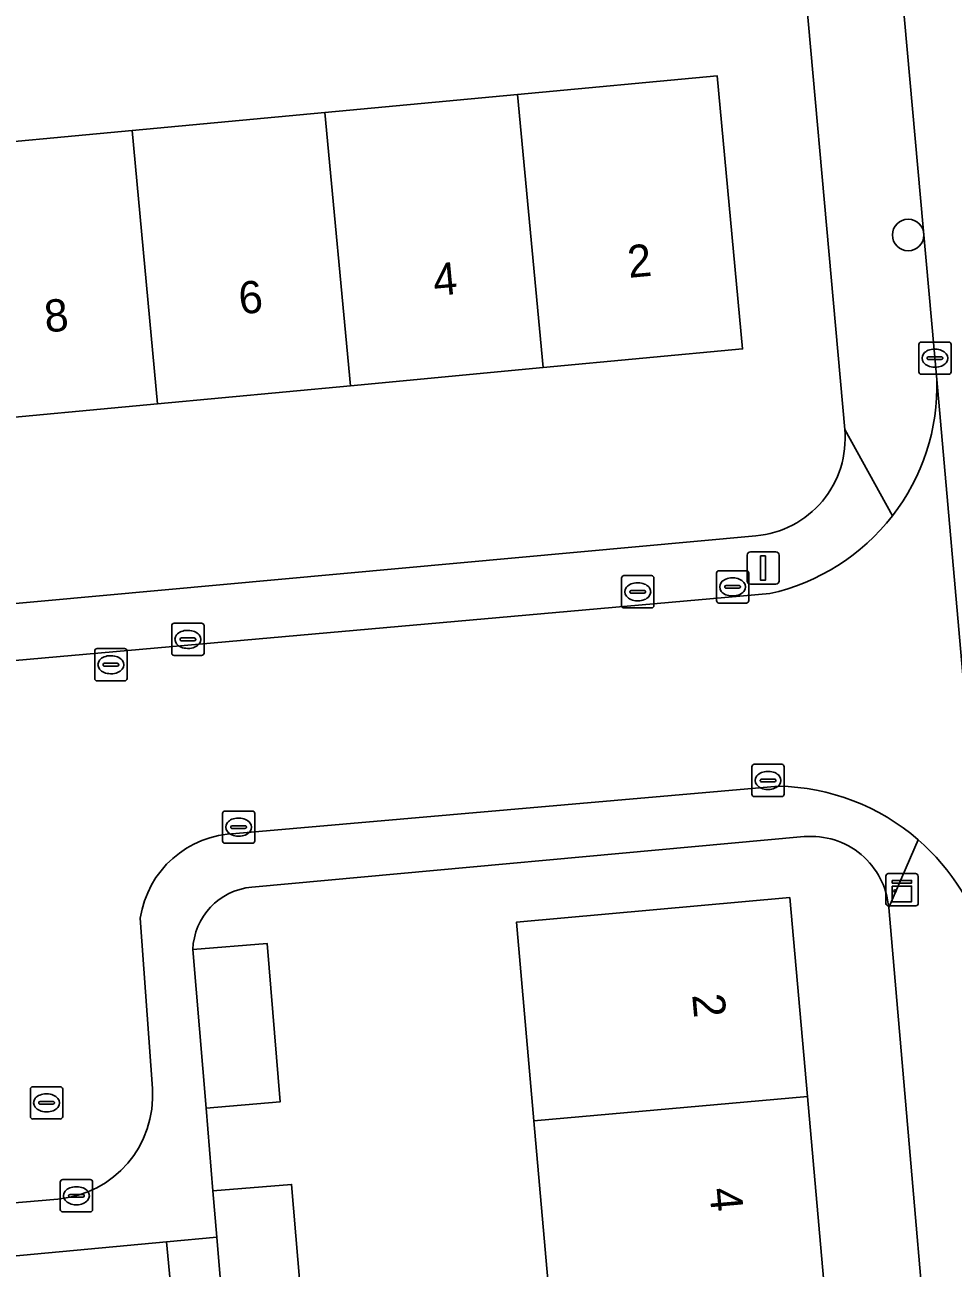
# Model space of a CAD drawing. Extents: x 160554 to 161248, y 385329 to 386506.
# Drawn here: x 160890.27 to 160919.04, y 385530.83 to 385569.34 of the extents above; entities that cross this region are included whole.
import ezdxf

# ---------------------------------------------------------------- set-up
doc = ezdxf.new("R2010")
doc.units = 0
for name, color, linetype in [('IMGEO_Boom', 7, 'Continuous'), ('IMGEO_Brandkraan', 7, 'Continuous'), ('IMGEO_Erf', 7, 'Continuous'), ('IMGEO_Kast', 7, 'Continuous'), ('IMGEO_Kolk', 7, 'Continuous'), ('IMGEO_Lichtmast', 7, 'Continuous'), ('IMGEO_Pand', 7, 'Continuous'), ('IMGEO_Pand_nummerreeks', 7, 'Continuous'), ('IMGEO_Rijbaan_lokaal_open', 7, 'Continuous'), ('IMGEO_Rioolput', 7, 'Continuous'), ('IMGEO_Voetpad_open', 7, 'Continuous')]:
    doc.layers.add(name, color=color, linetype=linetype)

msp = doc.modelspace()

# ---------------------------------------------------------------- linework, layer by layer
at = {"layer": 'IMGEO_Boom'}
msp.add_circle((160917.643, 385562.833), 0.489, dxfattribs=at)
at = {"layer": 'IMGEO_Brandkraan'}
for p, q in [((160908.835, 385552.279), (160909.687, 385552.279)), ((160908.76, 385551.353), (160908.76, 385552.205)), ((160909.248, 385552.059), (160909.273, 385552.059)), ((160909.761, 385552.205), (160909.761, 385551.353)), ((160909.019, 385551.773), (160909.019, 385551.785)), ((160909.457, 385551.736), (160909.059, 385551.736)), ((160909.062, 385551.822), (160909.46, 385551.822)), ((160909.271, 385551.499), (160909.246, 385551.499)), ((160909.503, 385551.785), (160909.503, 385551.773)), ((160909.687, 385551.279), (160908.835, 385551.279)), ((160892.431, 385549.094), (160892.431, 385549.946)), ((160892.506, 385550.02), (160893.358, 385550.02)), ((160893.432, 385549.946), (160893.432, 385549.094)), ((160892.733, 385549.563), (160893.131, 385549.563)), ((160892.919, 385549.8), (160892.944, 385549.8)), ((160892.69, 385549.514), (160892.69, 385549.526)), ((160893.128, 385549.477), (160892.73, 385549.477)), ((160892.942, 385549.24), (160892.917, 385549.24)), ((160893.174, 385549.526), (160893.174, 385549.514)), ((160893.358, 385549.02), (160892.506, 385549.02))]:
    msp.add_line(p, q, dxfattribs=at)
for points in [[(160908.835, 385552.279), (160909.687, 385552.279)], [(160908.76, 385551.353), (160908.76, 385552.205)], [(160909.761, 385552.205), (160909.761, 385551.353)], [(160909.687, 385551.279), (160908.835, 385551.279)], [(160892.431, 385549.094), (160892.431, 385549.946)], [(160892.506, 385550.02), (160893.358, 385550.02)], [(160893.432, 385549.946), (160893.432, 385549.094)], [(160893.358, 385549.02), (160892.506, 385549.02)]]:
    msp.add_lwpolyline(points, dxfattribs=at)
for centre, radius, start, end in [((160908.837, 385552.203), 0.0765, 91.552, 178.448), ((160908.837, 385552.203), 0.0765, 91.552, 178.448), ((160909.685, 385552.203), 0.0765, 1.552, 88.448), ((160909.685, 385552.203), 0.0765, 1.552, 88.448), ((160909.059, 385551.782), 0.0403, 85.8775, 175.7526), ((160909.056, 385551.772), 0.0366, 178.938, 274.7102), ((160909.46, 385551.779), 0.043, 264.8664, 352.4533), ((160909.464, 385551.784), 0.0386, 1.7309, 96.639), ((160908.837, 385551.355), 0.0765, 181.552, 268.448), ((160908.837, 385551.355), 0.0765, 181.552, 268.448), ((160909.685, 385551.355), 0.0765, 271.552, 358.448), ((160909.685, 385551.355), 0.0765, 271.552, 358.448), ((160892.508, 385549.944), 0.0765, 91.552, 178.448), ((160892.508, 385549.944), 0.0765, 91.552, 178.448), ((160893.356, 385549.944), 0.0765, 1.552, 88.448), ((160893.356, 385549.944), 0.0765, 1.552, 88.448), ((160892.73, 385549.523), 0.0403, 85.8775, 175.7526), ((160893.135, 385549.525), 0.0386, 1.7309, 96.639), ((160892.727, 385549.513), 0.0366, 178.938, 274.7102), ((160893.131, 385549.52), 0.043, 264.8664, 352.4533), ((160892.508, 385549.096), 0.0765, 181.552, 268.448), ((160892.508, 385549.096), 0.0765, 181.552, 268.448), ((160893.356, 385549.096), 0.0765, 271.552, 358.448), ((160893.356, 385549.096), 0.0765, 271.552, 358.448)]:
    msp.add_arc(centre, radius, start, end, dxfattribs=at)
for centre, major_axis, ratio, start_param, end_param in [((160909.247, 385551.779), (-0.387, 0.002), 0.722429, 4.712389, 7.853982), ((160909.272, 385551.779), (-0.39, 0.002), 0.717154, 1.570796, 4.712389), ((160892.918, 385549.52), (-0.387, 0.002), 0.722429, 4.712389, 7.853982), ((160892.943, 385549.52), (-0.39, 0.002), 0.717154, 1.570796, 4.712389)]:
    msp.add_ellipse(centre, major_axis=major_axis, ratio=ratio, start_param=start_param, end_param=end_param, dxfattribs=at)
at = {"layer": 'IMGEO_Erf'}
for points in [[(160915.678, 385556.807), (160914.058, 385574.884)], [(160861.315, 385572.826), (160862.693, 385557.771), (160864.008, 385557.909), (160863.508, 385563.248), (160869.693, 385563.827), (160875.667, 385564.387), (160875.425, 385566.97), (160881.399, 385567.53), (160881.641, 385564.947), (160887.615, 385565.506), (160893.588, 385566.066), (160899.562, 385566.625), (160905.536, 385567.185), (160911.72, 385567.764)], [(160911.72, 385567.764), (160912.513, 385559.301), (160906.329, 385558.722), (160900.355, 385558.162), (160894.381, 385557.603), (160888.408, 385557.043), (160882.434, 385556.484), (160876.46, 385555.924), (160870.486, 385555.364), (160864.477, 385554.802), (160864.993, 385549.134), (160912.922, 385553.512)], [(160914.423, 385544.194), (160897.297, 385542.63)], [(160922.169, 385482.49), (160920.66, 385500), (160917.04, 385541.995)], [(160895.471, 385540.695), (160897.773, 385540.887), (160898.182, 385535.98), (160895.88, 385535.788), (160896.095, 385533.221), (160898.533, 385533.424), (160898.921, 385528.774)], [(160895.014, 385527.83), (160894.659, 385531.64), (160866.822, 385529.049)]]:
    msp.add_lwpolyline(points, dxfattribs=at)
msp.add_lwpolyline([(160907.099, 385523.44), (160906.571, 385529.417), (160906.043, 385535.394), (160905.5, 385541.541), (160913.975, 385542.309), (160914.52, 385536.143), (160915.048, 385530.166), (160915.575, 385524.189), (160916.103, 385518.213), (160916.631, 385512.236), (160917.159, 385506.259), (160917.687, 385500.282), (160917.712, 385500), (160918.215, 385494.306), (160918.76, 385488.141), (160910.284, 385487.387), (160909.739, 385493.557), (160909.211, 385499.533), (160909.17, 385500), (160908.683, 385505.51), (160908.155, 385511.487), (160907.627, 385517.464)], close=True, dxfattribs=at)
for centre, radius, start, end in [((160912.657, 385556.534), 3.033, 275.0141, 5.1664), ((160914.634, 385541.789), 2.414, 4.8991, 95.0219), ((160897.488, 385540.621), 2.018, 95.4245, 177.8956)]:
    msp.add_arc(centre, radius, start, end, dxfattribs=at)
at = {"layer": 'IMGEO_Kast'}
for p, q in [((160917.028, 385543.05), (160917.869, 385543.05)), ((160917.869, 385543.05), (160917.028, 385543.05)), ((160916.953, 385542.125), (160916.953, 385542.966)), ((160916.953, 385542.966), (160916.953, 385542.125)), ((160917.953, 385542.975), (160917.953, 385542.134)), ((160917.953, 385542.134), (160917.953, 385542.975)), ((160917.878, 385542.05), (160917.037, 385542.05)), ((160917.037, 385542.05), (160917.878, 385542.05))]:
    msp.add_line(p, q, dxfattribs=at)
for points in [[(160917.148, 385542.84), (160917.748, 385542.84), (160917.748, 385542.755), (160917.148, 385542.755), (160917.148, 385542.84)], [(160917.148, 385542.665), (160917.748, 385542.665), (160917.748, 385542.176), (160917.148, 385542.176), (160917.148, 385542.665)]]:
    msp.add_lwpolyline(points, dxfattribs=at)
msp.add_circle((160917.232, 385542.514), 0.0377, dxfattribs=at)
for centre, start, end in [((160917.031, 385542.972), 92.4484, 184.2845), ((160917.031, 385542.972), 92.4484, 184.2845), ((160917.875, 385542.972), 2.4484, 94.2845), ((160917.875, 385542.972), 2.4484, 94.2845), ((160917.031, 385542.128), 182.4484, 274.2845), ((160917.031, 385542.128), 182.4484, 274.2845), ((160917.875, 385542.128), 272.4484, 4.2845), ((160917.875, 385542.128), 272.4484, 4.2845)]:
    msp.add_arc(centre, 0.0779, start, end, dxfattribs=at)
at = {"layer": 'IMGEO_Kolk'}
for p, q in [((160917.972, 385558.59), (160917.972, 385559.442)), ((160918.047, 385559.516), (160918.899, 385559.516)), ((160918.46, 385559.296), (160918.485, 385559.296)), ((160918.973, 385559.442), (160918.973, 385558.59)), ((160918.231, 385559.01), (160918.231, 385559.022)), ((160918.669, 385558.973), (160918.271, 385558.973)), ((160918.274, 385559.059), (160918.672, 385559.059)), ((160918.715, 385559.022), (160918.715, 385559.01)), ((160918.899, 385558.516), (160918.047, 385558.516)), ((160918.483, 385558.736), (160918.458, 385558.736)), ((160911.701, 385551.505), (160911.701, 385552.357)), ((160911.776, 385552.431), (160912.628, 385552.431)), ((160912.702, 385552.357), (160912.702, 385551.505)), ((160911.96, 385551.925), (160911.96, 385551.937)), ((160912.398, 385551.888), (160912, 385551.888)), ((160912.003, 385551.974), (160912.401, 385551.974)), ((160912.189, 385552.211), (160912.214, 385552.211)), ((160912.444, 385551.937), (160912.444, 385551.925)), ((160912.212, 385551.651), (160912.187, 385551.651)), ((160912.628, 385551.431), (160911.776, 385551.431)), ((160894.818, 385549.879), (160894.818, 385550.731)), ((160894.893, 385550.805), (160895.745, 385550.805)), ((160895.819, 385550.731), (160895.819, 385549.879)), ((160895.12, 385550.348), (160895.518, 385550.348)), ((160895.306, 385550.585), (160895.331, 385550.585)), ((160895.077, 385550.299), (160895.077, 385550.311)), ((160895.515, 385550.262), (160895.117, 385550.262)), ((160895.329, 385550.025), (160895.304, 385550.025)), ((160895.561, 385550.311), (160895.561, 385550.299)), ((160895.745, 385549.805), (160894.893, 385549.805)), ((160912.799, 385545.509), (160912.799, 385546.361)), ((160912.874, 385546.435), (160913.726, 385546.435)), ((160913.287, 385546.215), (160913.312, 385546.215)), ((160913.8, 385546.361), (160913.8, 385545.509)), ((160913.058, 385545.929), (160913.058, 385545.941)), ((160913.496, 385545.892), (160913.098, 385545.892)), ((160913.101, 385545.978), (160913.499, 385545.978)), ((160913.542, 385545.941), (160913.542, 385545.929)), ((160913.726, 385545.435), (160912.874, 385545.435)), ((160913.31, 385545.655), (160913.285, 385545.655)), ((160896.466, 385544.988), (160897.318, 385544.988)), ((160896.391, 385544.062), (160896.391, 385544.914)), ((160896.879, 385544.768), (160896.904, 385544.768)), ((160897.392, 385544.914), (160897.392, 385544.062)), ((160896.65, 385544.482), (160896.65, 385544.494)), ((160897.088, 385544.445), (160896.69, 385544.445)), ((160896.693, 385544.531), (160897.091, 385544.531)), ((160896.902, 385544.208), (160896.877, 385544.208)), ((160897.134, 385544.494), (160897.134, 385544.482)), ((160897.318, 385543.988), (160896.466, 385543.988)), ((160891.363, 385532.644), (160891.363, 385533.496)), ((160891.438, 385533.57), (160892.29, 385533.57)), ((160892.364, 385533.496), (160892.364, 385532.644)), ((160891.622, 385533.064), (160891.622, 385533.076)), ((160892.06, 385533.027), (160891.662, 385533.027)), ((160891.665, 385533.113), (160892.063, 385533.113)), ((160891.851, 385533.35), (160891.876, 385533.35)), ((160892.106, 385533.076), (160892.106, 385533.064)), ((160891.874, 385532.79), (160891.849, 385532.79)), ((160892.29, 385532.57), (160891.438, 385532.57))]:
    msp.add_line(p, q, dxfattribs=at)
for points in [[(160917.972, 385558.59), (160917.972, 385559.442)], [(160918.047, 385559.516), (160918.899, 385559.516)], [(160918.973, 385559.442), (160918.973, 385558.59)], [(160918.899, 385558.516), (160918.047, 385558.516)], [(160911.701, 385551.505), (160911.701, 385552.357)], [(160911.776, 385552.431), (160912.628, 385552.431)], [(160912.702, 385552.357), (160912.702, 385551.505)], [(160912.628, 385551.431), (160911.776, 385551.431)], [(160894.818, 385549.879), (160894.818, 385550.731)], [(160894.893, 385550.805), (160895.745, 385550.805)], [(160895.819, 385550.731), (160895.819, 385549.879)], [(160895.745, 385549.805), (160894.893, 385549.805)], [(160912.799, 385545.509), (160912.799, 385546.361)], [(160912.874, 385546.435), (160913.726, 385546.435)], [(160913.8, 385546.361), (160913.8, 385545.509)], [(160913.726, 385545.435), (160912.874, 385545.435)], [(160896.466, 385544.988), (160897.318, 385544.988)], [(160896.391, 385544.062), (160896.391, 385544.914)], [(160897.392, 385544.914), (160897.392, 385544.062)], [(160897.318, 385543.988), (160896.466, 385543.988)], [(160891.363, 385532.644), (160891.363, 385533.496)], [(160891.438, 385533.57), (160892.29, 385533.57)], [(160892.364, 385533.496), (160892.364, 385532.644)], [(160892.29, 385532.57), (160891.438, 385532.57)]]:
    msp.add_lwpolyline(points, dxfattribs=at)
for centre, radius, start, end in [((160918.049, 385559.44), 0.0765, 91.552, 178.448), ((160918.049, 385559.44), 0.0765, 91.552, 178.448), ((160918.897, 385559.44), 0.0765, 1.552, 88.448), ((160918.897, 385559.44), 0.0765, 1.552, 88.448), ((160918.271, 385559.019), 0.0403, 85.8775, 175.7526), ((160918.268, 385559.009), 0.0366, 178.938, 274.7102), ((160918.672, 385559.016), 0.043, 264.8664, 352.4533), ((160918.676, 385559.021), 0.0386, 1.7309, 96.639), ((160918.049, 385558.592), 0.0765, 181.552, 268.448), ((160918.049, 385558.592), 0.0765, 181.552, 268.448), ((160918.897, 385558.592), 0.0765, 271.552, 358.448), ((160918.897, 385558.592), 0.0765, 271.552, 358.448), ((160911.778, 385552.355), 0.0765, 91.552, 178.448), ((160911.778, 385552.355), 0.0765, 91.552, 178.448), ((160912.626, 385552.355), 0.0765, 1.552, 88.448), ((160912.626, 385552.355), 0.0765, 1.552, 88.448), ((160912, 385551.934), 0.0403, 85.8775, 175.7526), ((160911.997, 385551.924), 0.0366, 178.938, 274.7102), ((160912.401, 385551.931), 0.043, 264.8664, 352.4533), ((160912.405, 385551.936), 0.0386, 1.7309, 96.639), ((160911.778, 385551.507), 0.0765, 181.552, 268.448), ((160911.778, 385551.507), 0.0765, 181.552, 268.448), ((160912.626, 385551.507), 0.0765, 271.552, 358.448), ((160912.626, 385551.507), 0.0765, 271.552, 358.448), ((160894.895, 385550.729), 0.0765, 91.552, 178.448), ((160894.895, 385550.729), 0.0765, 91.552, 178.448), ((160895.743, 385550.729), 0.0765, 1.552, 88.448), ((160895.743, 385550.729), 0.0765, 1.552, 88.448), ((160895.117, 385550.308), 0.0403, 85.8775, 175.7526), ((160895.522, 385550.31), 0.0386, 1.7309, 96.639), ((160895.114, 385550.298), 0.0366, 178.938, 274.7102), ((160895.518, 385550.305), 0.043, 264.8664, 352.4533), ((160894.895, 385549.881), 0.0765, 181.552, 268.448), ((160894.895, 385549.881), 0.0765, 181.552, 268.448), ((160895.743, 385549.881), 0.0765, 271.552, 358.448), ((160895.743, 385549.881), 0.0765, 271.552, 358.448), ((160912.876, 385546.359), 0.0765, 91.552, 178.448), ((160912.876, 385546.359), 0.0765, 91.552, 178.448), ((160913.724, 385546.359), 0.0765, 1.552, 88.448), ((160913.724, 385546.359), 0.0765, 1.552, 88.448), ((160913.098, 385545.938), 0.0403, 85.8775, 175.7526), ((160913.095, 385545.928), 0.0366, 178.938, 274.7102), ((160913.499, 385545.935), 0.043, 264.8664, 352.4533), ((160913.503, 385545.94), 0.0386, 1.7309, 96.639), ((160912.876, 385545.511), 0.0765, 181.552, 268.448), ((160912.876, 385545.511), 0.0765, 181.552, 268.448), ((160913.724, 385545.511), 0.0765, 271.552, 358.448), ((160913.724, 385545.511), 0.0765, 271.552, 358.448), ((160896.468, 385544.912), 0.0765, 91.552, 178.448), ((160896.468, 385544.912), 0.0765, 91.552, 178.448), ((160897.316, 385544.912), 0.0765, 1.552, 88.448), ((160897.316, 385544.912), 0.0765, 1.552, 88.448), ((160896.69, 385544.491), 0.0403, 85.8775, 175.7526), ((160896.687, 385544.481), 0.0366, 178.938, 274.7102), ((160897.091, 385544.488), 0.043, 264.8664, 352.4533), ((160897.095, 385544.493), 0.0386, 1.7309, 96.639), ((160896.468, 385544.064), 0.0765, 181.552, 268.448), ((160896.468, 385544.064), 0.0765, 181.552, 268.448), ((160897.316, 385544.064), 0.0765, 271.552, 358.448), ((160897.316, 385544.064), 0.0765, 271.552, 358.448), ((160891.44, 385533.494), 0.0765, 91.552, 178.448), ((160891.44, 385533.494), 0.0765, 91.552, 178.448), ((160892.288, 385533.494), 0.0765, 1.552, 88.448), ((160892.288, 385533.494), 0.0765, 1.552, 88.448), ((160891.662, 385533.073), 0.0403, 85.8775, 175.7526), ((160891.659, 385533.063), 0.0366, 178.938, 274.7102), ((160892.063, 385533.07), 0.043, 264.8664, 352.4533), ((160892.067, 385533.075), 0.0386, 1.7309, 96.639), ((160891.44, 385532.646), 0.0765, 181.552, 268.448), ((160891.44, 385532.646), 0.0765, 181.552, 268.448), ((160892.288, 385532.646), 0.0765, 271.552, 358.448), ((160892.288, 385532.646), 0.0765, 271.552, 358.448)]:
    msp.add_arc(centre, radius, start, end, dxfattribs=at)
for centre, major_axis, ratio, start_param, end_param in [((160918.459, 385559.016), (-0.387, 0.002), 0.722429, 4.712389, 7.853982), ((160918.484, 385559.016), (-0.39, 0.002), 0.717154, 1.570796, 4.712389), ((160912.188, 385551.931), (-0.387, 0.002), 0.722429, 4.712389, 7.853982), ((160912.213, 385551.931), (-0.39, 0.002), 0.717154, 1.570796, 4.712389), ((160895.305, 385550.305), (-0.387, 0.002), 0.722429, 4.712389, 7.853982), ((160895.33, 385550.305), (-0.39, 0.002), 0.717154, 1.570796, 4.712389), ((160913.286, 385545.935), (-0.387, 0.002), 0.722429, 4.712389, 7.853982), ((160913.311, 385545.935), (-0.39, 0.002), 0.717154, 1.570796, 4.712389), ((160896.878, 385544.488), (-0.387, 0.002), 0.722429, 4.712389, 7.853982), ((160896.903, 385544.488), (-0.39, 0.002), 0.717154, 1.570796, 4.712389), ((160891.85, 385533.07), (-0.387, 0.002), 0.722429, 4.712389, 7.853982), ((160891.875, 385533.07), (-0.39, 0.002), 0.717154, 1.570796, 4.712389)]:
    msp.add_ellipse(centre, major_axis=major_axis, ratio=ratio, start_param=start_param, end_param=end_param, dxfattribs=at)
at = {"layer": 'IMGEO_Lichtmast'}
for p, q in [((160912.651, 385552.113), (160912.651, 385552.913)), ((160912.651, 385552.913), (160912.651, 385552.113)), ((160912.751, 385553.013), (160913.541, 385553.013)), ((160913.541, 385553.013), (160912.751, 385553.013)), ((160913.641, 385552.913), (160913.641, 385552.113)), ((160913.641, 385552.113), (160913.641, 385552.913)), ((160913.541, 385552.013), (160912.751, 385552.013)), ((160912.751, 385552.013), (160913.541, 385552.013))]:
    msp.add_line(p, q, dxfattribs=at)
msp.add_lwpolyline([(160913.071, 385552.888), (160913.221, 385552.888), (160913.221, 385552.138), (160913.071, 385552.138), (160913.071, 385552.888)], dxfattribs=at)
for centre, start, end in [((160912.751, 385552.913), 90, 180), ((160912.751, 385552.913), 90, 180), ((160913.541, 385552.913), 0, 90), ((160913.541, 385552.913), 360, 90), ((160912.751, 385552.113), 180, 270), ((160912.751, 385552.113), 180, 270), ((160913.541, 385552.113), 270, 0), ((160913.541, 385552.113), 270, 0)]:
    msp.add_arc(centre, 0.1, start, end, dxfattribs=at)
at = {"layer": 'IMGEO_Pand'}
for points in [[(160906.329, 385558.722), (160912.513, 385559.301), (160911.72, 385567.764), (160905.536, 385567.185)], [(160905.536, 385567.185), (160899.562, 385566.625), (160900.355, 385558.162), (160906.329, 385558.722)], [(160899.562, 385566.625), (160893.588, 385566.066), (160894.381, 385557.603), (160900.355, 385558.162)], [(160893.588, 385566.066), (160887.615, 385565.506), (160888.408, 385557.043), (160894.381, 385557.603)], [(160914.52, 385536.143), (160913.975, 385542.309), (160905.5, 385541.541), (160906.043, 385535.394)], [(160895.88, 385535.788), (160898.182, 385535.98), (160897.773, 385540.887), (160895.471, 385540.695)], [(160906.043, 385535.394), (160906.571, 385529.417), (160915.048, 385530.166), (160914.52, 385536.143)], [(160896.215, 385531.785), (160896.484, 385528.559), (160898.921, 385528.774), (160898.533, 385533.424), (160896.095, 385533.221)]]:
    msp.add_lwpolyline(points, close=True, dxfattribs=at)
at = {"layer": 'IMGEO_Rijbaan_lokaal_open'}
for points in [[(160925.621, 385558.308), (160924.059, 385575.413), (160923.718, 385579.136), (160923.487, 385581.67), (160921.484, 385603.875), (160921.344, 385605.542), (160914.387, 385604.81), (160914.572, 385603.534), (160914.741, 385601.627), (160916.313, 385583.041), (160916.536, 385580.505), (160916.636, 385579.396), (160916.744, 385578.2), (160917.103, 385574.214), (160918.533, 385558.353), (160920.088, 385540.64), (160921.02, 385529.968), (160921.23, 385527.569), (160921.415, 385525.719), (160922.559, 385513.431)], [(160920.088, 385540.64), (160918.533, 385558.353)], [(160913.355, 385551.724), (160871.806, 385548.04)], [(160896.809, 385544.291), (160913.629, 385545.756)], [(160894.217, 385536.396), (160893.843, 385541.672)], [(160873.261, 385531.435), (160891.284, 385532.967)]]:
    msp.add_lwpolyline(points, dxfattribs=at)
for centre, radius, start, end in [((160911.935, 385558.171), 6.601, 322.238, 1.5771), ((160911.935, 385558.168), 6.598, 282.4267, 322.2596), ((160913.502, 385538.955), 6.802, 49.1441, 88.9266), ((160896.891, 385541.209), 3.083, 91.5249, 171.3646), ((160913.5, 385538.961), 6.798, 14.297, 49.1044), ((160891.013, 385536.168), 3.212, 274.8457, 4.0702)]:
    msp.add_arc(centre, radius, start, end, dxfattribs=at)
at = {"layer": 'IMGEO_Rioolput'}
for p, q in [((160890.437, 385535.522), (160890.437, 385536.374)), ((160890.512, 385536.448), (160891.364, 385536.448)), ((160890.925, 385536.228), (160890.95, 385536.228)), ((160891.438, 385536.374), (160891.438, 385535.522)), ((160890.696, 385535.942), (160890.696, 385535.954)), ((160891.134, 385535.905), (160890.736, 385535.905)), ((160890.739, 385535.991), (160891.137, 385535.991)), ((160891.18, 385535.954), (160891.18, 385535.942)), ((160891.364, 385535.448), (160890.512, 385535.448)), ((160890.948, 385535.668), (160890.923, 385535.668))]:
    msp.add_line(p, q, dxfattribs=at)
for points in [[(160890.437, 385535.522), (160890.437, 385536.374)], [(160890.512, 385536.448), (160891.364, 385536.448)], [(160891.438, 385536.374), (160891.438, 385535.522)], [(160891.364, 385535.448), (160890.512, 385535.448)]]:
    msp.add_lwpolyline(points, dxfattribs=at)
for centre, radius, start, end in [((160890.514, 385536.372), 0.0765, 91.552, 178.448), ((160890.514, 385536.372), 0.0765, 91.552, 178.448), ((160891.362, 385536.372), 0.0765, 1.552, 88.448), ((160891.362, 385536.372), 0.0765, 1.552, 88.448), ((160890.736, 385535.951), 0.0403, 85.8775, 175.7526), ((160890.733, 385535.941), 0.0366, 178.938, 274.7102), ((160891.137, 385535.948), 0.043, 264.8664, 352.4533), ((160891.141, 385535.953), 0.0386, 1.7309, 96.639), ((160890.514, 385535.524), 0.0765, 181.552, 268.448), ((160890.514, 385535.524), 0.0765, 181.552, 268.448), ((160891.362, 385535.524), 0.0765, 271.552, 358.448), ((160891.362, 385535.524), 0.0765, 271.552, 358.448)]:
    msp.add_arc(centre, radius, start, end, dxfattribs=at)
for centre, major_axis, ratio, start_param, end_param in [((160890.924, 385535.948), (-0.387, 0.002), 0.722429, 4.712389, 7.853982), ((160890.949, 385535.948), (-0.39, 0.002), 0.717154, 1.570796, 4.712389)]:
    msp.add_ellipse(centre, major_axis=major_axis, ratio=ratio, start_param=start_param, end_param=end_param, dxfattribs=at)
at = {"layer": 'IMGEO_Voetpad_open'}
for points in [[(160911.465, 385603.818), (160913.071, 385585.893), (160913.218, 385584.262), (160913.415, 385582.06), (160913.661, 385579.318), (160913.808, 385577.673), (160914.058, 385574.884), (160915.678, 385556.807), (160917.153, 385554.129)], [(160918.533, 385558.353), (160917.103, 385574.214), (160916.744, 385578.2), (160916.636, 385579.396), (160916.536, 385580.505)], [(160917.153, 385554.129), (160915.678, 385556.807)], [(160912.922, 385553.512), (160864.993, 385549.134), (160863.436, 385548.992), (160864.998, 385530.768), (160865.469, 385525.276), (160867.099, 385525.38), (160866.822, 385529.049), (160894.659, 385531.64), (160896.215, 385531.785), (160896.095, 385533.221), (160895.88, 385535.788), (160895.471, 385540.695)], [(160871.806, 385548.04), (160913.355, 385551.724)], [(160913.629, 385545.756), (160896.809, 385544.291)], [(160897.297, 385542.63), (160914.423, 385544.194)], [(160917.951, 385544.1), (160917.04, 385541.995), (160920.66, 385500), (160922.169, 385482.49), (160925.231, 385482.784), (160923.776, 385500), (160923.539, 385502.802), (160922.751, 385512.494)], [(160917.04, 385541.995), (160917.951, 385544.1)], [(160893.843, 385541.672), (160894.217, 385536.396)], [(160891.284, 385532.967), (160873.261, 385531.435)], [(160896.484, 385528.559), (160896.215, 385531.785), (160894.659, 385531.64), (160895.014, 385527.83)]]:
    msp.add_lwpolyline(points, dxfattribs=at)
for centre, radius, start, end in [((160911.935, 385558.171), 6.601, 322.238, 1.5771), ((160912.657, 385556.534), 3.033, 275.0141, 5.1664), ((160911.935, 385558.168), 6.598, 282.4267, 322.2596), ((160913.502, 385538.955), 6.802, 49.1441, 88.9266), ((160896.891, 385541.209), 3.083, 91.5249, 171.3646), ((160914.634, 385541.789), 2.414, 4.8991, 95.0219), ((160913.5, 385538.961), 6.798, 14.297, 49.1044), ((160897.488, 385540.621), 2.018, 95.4245, 177.8956), ((160891.013, 385536.168), 3.212, 274.8457, 4.0702)]:
    msp.add_arc(centre, radius, start, end, dxfattribs=at)

# ---------------------------------------------------------------- texts
at = {"layer": 'IMGEO_Pand_nummerreeks'}
for s, rotation, p in [('2', 5.3511, (160908.988, 385561.502)), ('4', 5.3511, (160902.964, 385560.938)), ('6', 5.3511, (160896.937, 385560.373)), ('8', 5.3511, (160890.914, 385559.809)), ('2', 275.0475, (160910.948, 385539.295)), ('4', 275.0475, (160911.479, 385533.289))]:
    msp.add_text(s, height=1, rotation=rotation, dxfattribs=at).set_placement(p)

doc.saveas('drawing.dxf')
